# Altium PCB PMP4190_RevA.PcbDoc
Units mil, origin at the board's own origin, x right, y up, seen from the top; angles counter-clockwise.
Board outline 2303.15 x 1259.84 mil, 2 copper layers (Top Layer, Bottom Layer), stack 62 mil thick; 41 components, 17 nets, 91 pads, 28 vias.
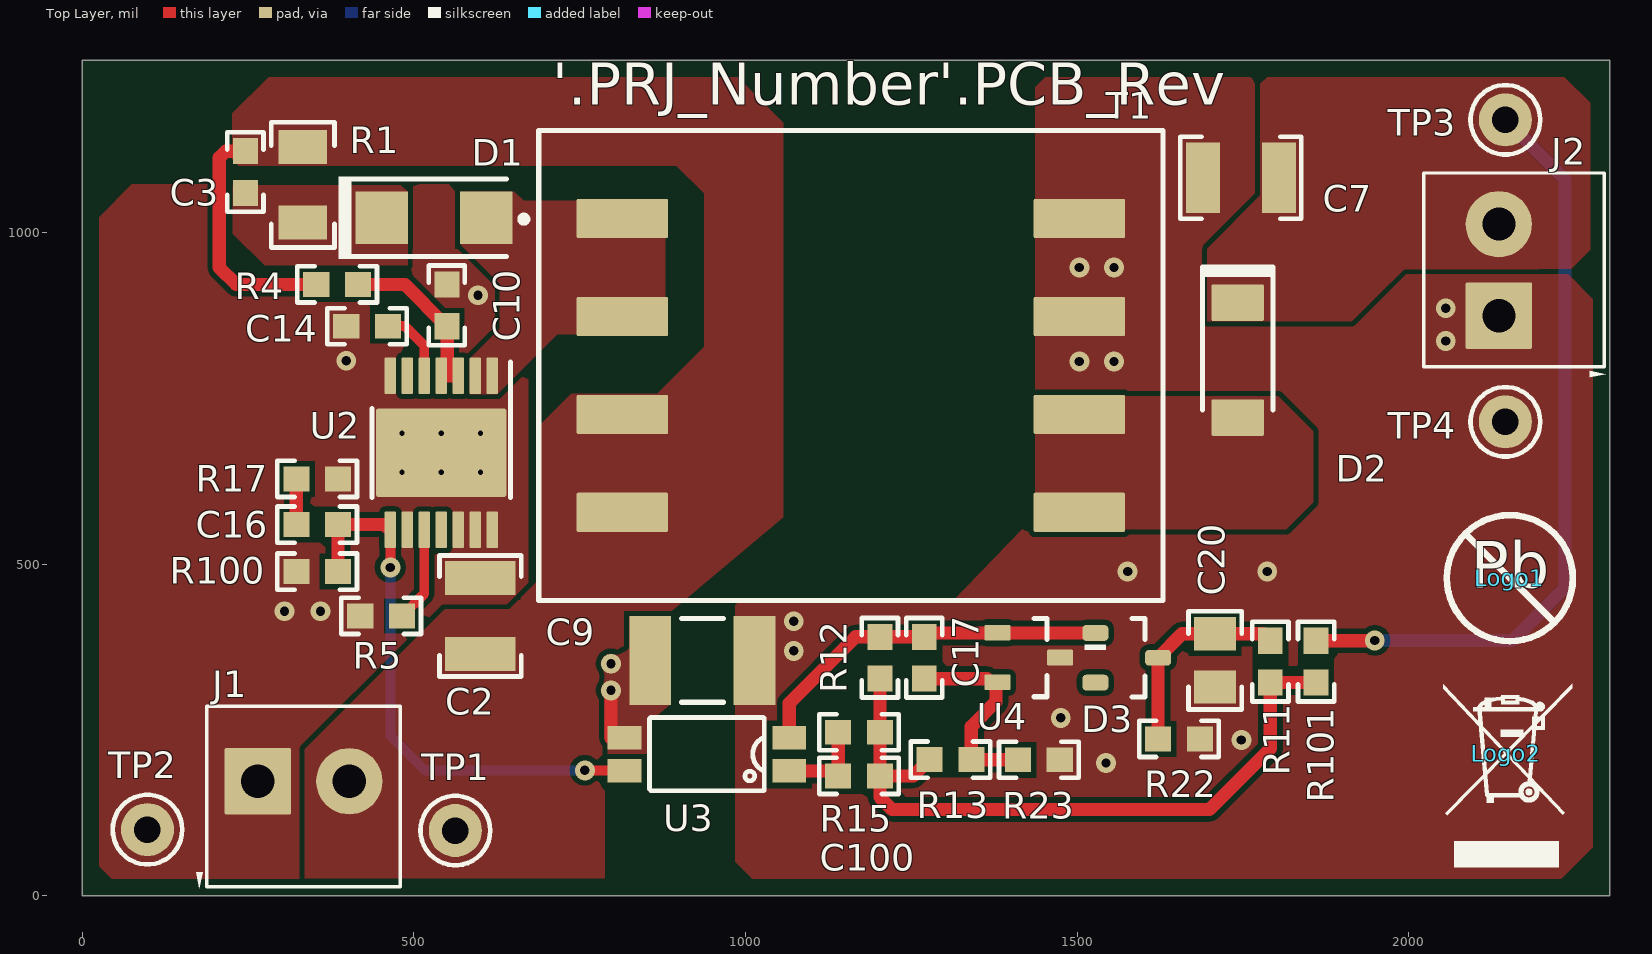
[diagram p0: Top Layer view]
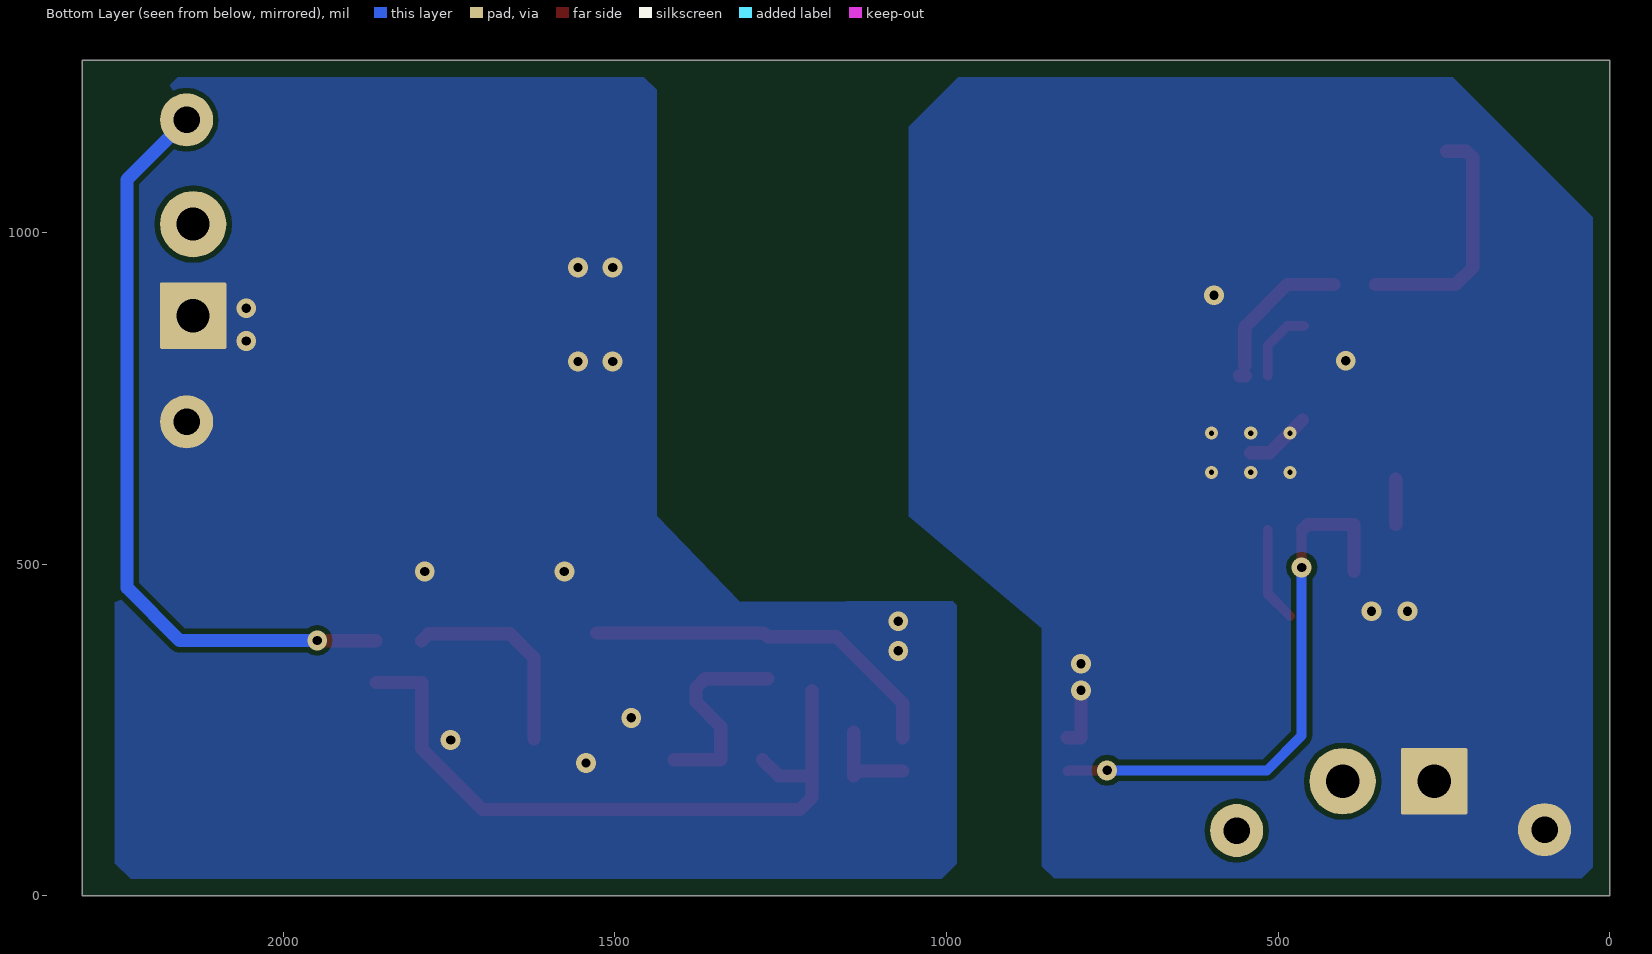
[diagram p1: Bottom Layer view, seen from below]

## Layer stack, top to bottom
Top Solder: solder mask 0.4, Solder Resist, Dk 3.5
Top Layer: signal copper 1.4
Dielectric1: core 59.2, FR-4, Dk 4.8
Bottom Layer: signal copper 1.4
Bottom Solder: solder mask 0.4, Solder Resist, Dk 3.5

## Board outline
0,0 2303.15,0 2303.15,1259.84 0,1259.84

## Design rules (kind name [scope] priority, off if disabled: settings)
AcuteAngle [All] p1: minimum=4.50000000000000E+0001 checktracksonly=FALSE
AssemblyTestPointUsage [All] p1: valid=2
BoardOutlineClearance BoardOutlineClearance_MountingHoles [OnCopper and InComponentClass('Mounting Holes')] p1: gap=25 ignorepadtopadclearanceinfootprint=FALSE
BoardOutlineClearance BoardOutlineClearance_Poly [OnCopper and InPoly] p2: gap=25 ignorepadtopadclearanceinfootprint=FALSE
BoardOutlineClearance [OnCopper and Not InComponentClass('Logo') and not InComponentClass('FiducialMark') and not InRegion(1000,500,4000,800)] p3: gap=25 ignorepadtopadclearanceinfootprint=FALSE
Clearance Clearance_Keepouts [((IsTrack Or IsArc) And Not InPoly) And IsFree and IsKeepOut vs ((IsTrack Or IsArc) And Not InPoly) And IsFree and IsKeepOut] p1: gap=0 ignorepadtopadclearanceinfootprint=FALSE
Clearance Clearance_Poly [InPolygon] p2: gap=8 ignorepadtopadclearanceinfootprint=FALSE except(0: Arc-Hole Track-Hole SMDPad-Hole THPad-Hole Via-Hole Fill-Hole Poly-Hole Region-Hole Text-Hole)
Clearance [All] p3: gap=7.87 ignorepadtopadclearanceinfootprint=FALSE except(0: Arc-Hole Track-Hole SMDPad-Hole THPad-Hole Via-Hole Fill-Hole Poly-Hole Region-Hole Text-Hole)
ComponentClearance ComponentClearance_MountingHoles_FiducialMarks [InComponentClass('Mounting Holes') vs InComponentClass('FiducialMark')] p1: gap=50 collisioncheckmode=3 verticalgap=10 showdistances=FALSE
ComponentClearance ComponentClearance_Shunt [InComponentClass('Header') vs InComponentClass('Shunt')] p2: gap=0 collisioncheckmode=3 verticalgap=0 showdistances=FALSE
ComponentClearance ComponentClearance_Logo [InComponentClass('Logo')] p3: gap=50 collisioncheckmode=3 verticalgap=10 showdistances=FALSE
ComponentClearance ComponentClearance_ScrewToNut [(HasFootprint('NY PMS 440 0025 PH')) vs (HasFootprint('Keystone_1902C'))] p4: gap=5 collisioncheckmode=3 verticalgap=10 showdistances=FALSE
ComponentClearance ComponentClearance_MountingHoles [InComponentClass('Mounting Holes')] p5: gap=250 collisioncheckmode=3 verticalgap=100000 showdistances=FALSE
ComponentClearance ComponentClearance_SmallPassives [HasFootprint('0201*') or HasFootprint('0402*') or HasFootprint('0508') or HasFootprint('0603*') or HasFootprint('0612') or HasFootprint('0805*') or HasFootprint('0815*') or HasFootprint('0830*') or HasFootprint('1206*') or HasFootprint('1210*') or HasFootprint('1808*') or HasFootprint('1812*') or HasFootprint('1825*') or HasFootprint('2010*') or HasFootprint('2220*') or HasFootprint('2225*') or HasFootprint('2512*') or HasFootprint('2728*') or HasFootprint('3518*') vs HasFootprint('0201*') or HasFootprint('0402*') or HasFootprint('0508') or HasFootprint('0603*') or HasFootprint('0612') or HasFootprint('0805*') or HasFootprint('0815*') or HasFootprint('0830*') or HasFootprint('1206*') or HasFootprint('1210*') or HasFootprint('1808*') or HasFootprint('1812*') or HasFootprint('1825*') or HasFootprint('2010*') or HasFootprint('2220*') or HasFootprint('2225*') or HasFootprint('2512*') or HasFootprint('2728*') or HasFootprint('3518*')] p6: gap=14.96 collisioncheckmode=3 verticalgap=10 showdistances=FALSE
ComponentClearance ComponentClearance_THtoSMT [IsThruComponent vs IsSMTComponent] p7: gap=15 collisioncheckmode=3 verticalgap=30 showdistances=FALSE
ComponentClearance ComponentClearance_THtoTH [IsThruComponent vs IsThruComponent] p8: gap=15 collisioncheckmode=3 verticalgap=30 showdistances=FALSE
ComponentClearance [All] p9: gap=15 collisioncheckmode=3 verticalgap=10 showdistances=FALSE
DiffPairsRouting [All] p1: maxlimit=100 minlimit=10 mostfreqgap=10 toplayer_minwidth=15 toplayer_maxwidth=15 toplayer_prefwidth=15 bottomlayer_minwidth=15 bottomlayer_maxwidth=15 bottomlayer_prefwidth=15 maxuncoupledlength=1000
FabricationTestPointUsage TestPointUsage [All] p1: valid=2 allowmultiple=FALSE
FabricationTestpoint Testpoint [All] p1: side=3 testpointundercomponent=TRUE minsize=40 maxsize=100 preferedsize=60 minholesize=0 maxholesize=40 preferedholesize=32 testpointgrid=1 allowsidetop=TRUE allowsidebottom=TRUE usegrid=TRUE gridtolerance=0.01
FanoutControl Fanout_LCC [IsLCC] p1: bgadir=Out bgaviamode=Centered fanoutstyle=Auto fanoutdirection=Alternating viagrid=1 // Fanout_LCC (Default Rule)
FanoutControl Fanout_BGA [IsBGA] p2: bgadir=Out bgaviamode=Centered fanoutstyle=Auto fanoutdirection=Alternating viagrid=1 // Fanout_BGA (Default Rule)
FanoutControl Fanout_Default [All] p4: bgadir=Out bgaviamode=Centered fanoutstyle=Auto fanoutdirection=Alternating viagrid=1 // Fanout_Default (Default Rule)
FanoutControl Fanout_Small [(CompPinCount < 5)] p5: bgadir=Out bgaviamode=Centered fanoutstyle=Auto fanoutdirection=OutThenIn viagrid=1 // Fanout_Small (Default Rule)
HoleSize [All] p1: absolutevalues=TRUE maxlimit=251 minlimit=7.87 maxpercent=80.000 minpercent=20.000
MinimumAnnularRing MinimumAnnularRing_ThermalPadVias [IsVia and InAnyComponent] p1: minimumring=5.91
MinimumAnnularRing [All] p2: minimumring=8
MinimumSolderMaskSliver MinimumSolderMaskSliver_Logo [InComponentClass('Logo') vs InComponentClass('Logo')] p1: minsoldermaskwidth=0.7
MinimumSolderMaskSliver [All] p2: minsoldermaskwidth=3.94
PlaneConnect [All] p1: planeconnectstyle=Direct reliefexpansion=10 reliefentries=4 reliefconductorwidth=10 reliefairgap=10
PolygonConnect [All] p1: connectstyle=Direct reliefconductorwidth=10 reliefentries=4 polygonreliefangle="90 Angle" airgapwidth=10
RoutingVias ThermalPadVias [IsVia and InAnyComponent] p1: holewidth=7.87 width=19.68 viastyle="Through Hole" minholewidth=7.87 minwidth=19.68 maxholewidth=12.99 maxwidth=23.62
RoutingVias [All] p2: holewidth=16 width=34 viastyle="Through Hole" minholewidth=7.87 minwidth=26 maxholewidth=40 maxwidth=65
SilkToBoardRegionClearance [Not ((IsComment or IsDesignator) And (Hide <> 'False')) and not InRegion(1000,500,4000,800)] p1:
SilkToSilkClearance SilkToSilkClearance_Pb-FreeLogo [(HasFootprint('Pb-Free_Overlay_Medium') OR HasFootprint('Pb-Free_Overlay_Small')) vs (HasFootprint('Pb-Free_Overlay_Medium') OR HasFootprint('Pb-Free_Overlay_Small'))] p1: silktosilkclearance=0
SilkToSilkClearance [All] p2: silktosilkclearance=4
SilkToSolderMaskClearance SilkToComponentPadClearance [IsPad and InAnycomponent] p1: minsilkscreentomaskgap=5 clearancetoexposedcopper=TRUE
SilkToSolderMaskClearance "Silk to Solder Mask Opening" [All] p2: minsilkscreentomaskgap=4 clearancetoexposedcopper=FALSE
SolderMaskExpansion [All] p1: expansion=1.97
Width [All] p1: maxlimit=100 minlimit=6 preferedwidth=10 checkconnectedcopper=TRUE
15 further rules are at their usual default settings.

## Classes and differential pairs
component class PMP4190_RevA: C2 C3 C7 C9 C10 C14 C16 C17 C20 C100 D1 D2 D3 J1 J2 R1 R4 R5 R11 R12 R13 R15 R17 R22 R23 R100 R101 T1 TP1 TP2 TP3 TP4 U2 U3 U4
component class Hardware: Logo1 Logo2 ZZ1 ZZ2 ZZ3 ZZ4
component class AssemblyNote: ZZ1 ZZ2 ZZ3 ZZ4

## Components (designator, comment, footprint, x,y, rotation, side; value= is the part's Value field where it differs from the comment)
C2 "GRM32ER71A226ME20L" 1210_270 600.39,421.91 r90 top value=22uF
C3 "C0603C102K5RACTU" 0603 246.06,1091.18 r270 top value=1000pF
C7 "GRM32ER71A226ME20L" 1210_270 1746.97,1082.68 r180 top value=22uF
C9 "1812GC472KA1" 1812 935.04,354.98 r180 top value=4700pF
C10 "C1608X7R1H104K080AA" 0603 549.79,890.27 r90 top value=0.1uF
C14 "CL10B101KB8NNNC" 0603 429.57,858.77 r180 top value=100pF
C16 "CGJ3E1X7R1E105K080AC" 0603 354.33,559.69 r180 top value=1uF
C17 "885012206089" 0603 1269.68,358.9 r270 top value=0.01uF
C20 "885012207025" 0805_HV 1707.97,354.98 r270 top value=4.7uF
C100 "C0603X223K5RACTU" 0603 1171.26,180.75 r180 top value=0.022uF
D1 "ES1B-13-F" SMA 530.35,1022.29 r0 top value=100V
D2 "RBS1LAM40ATR" FP-RBS1LAM40ATR_SOD128-MFG 1742.13,807.62 r270 top
D3 "BAS16LT1G" SOT-23 1574.8,358.9 r0 top value=100V
J1 "ED555/2DS" TERM_BLK_ED555-2DS 264.76,172.73 r0 top
J2 "ED555/2DS" TERM_BLK_ED555-2DS 2135.83,874.65 r90 top
Logo1 "Pb-Free Symbol" Pb-Free_Overlay_Medium 2152.48,478.99 r0 top
Logo2 "WEEE logo" WEEE_Minimum 2147.2,214.98 r0 top
R1 "RC1206FR-071KL" 1206 332.68,1071.98 r90 top value=1.00k
R4 "RC0603FR-0710RL" 0603 384.47,921.77 r180 top value=10.0
R5 "RC0603FR-0790K9L" 0603 450.79,421.91 r0 top value=90.9k
R11 "RC0603FR-071KL" 0603 1791.34,352.99 r270 top value=1.00k
R12 "RC0603FR-072KL" 0603 1202.76,358.9 r270 top value=2.00k
R13 "RC0603FR-0720KL" 0603 1309.06,205.36 r180 top value=20.0k
R15 "RC0603FR-07499RL" 0603 1171.26,246.69 r0 top value=499
R17 "RC0603FR-07499RL" 0603 354.33,628.58 r180 top value=499
R22 "RC0603FR-0710KL" 0603 1653.54,236.48 r180 top value=10.0k
R23 "RC0603FR-0720KL" 0603 1442.32,205.02 r0 top value=20.0k
R100 "RC0603FR-0749K9L" 0603 354.33,488.82 r0 top value=49.9k
R101 "RMCF0603ZT0R00" 0603 1860.24,352.99 r90 top value=0
T1 "G084001LF" FP-G084001LF_SMD8-MFG 1158.92,799.64 r270 top
TP1 "5000" Keystone5000 562.6,98.43 r90 top
TP2 "5001" Keystone5001 98.43,99.76 r90 top
TP3 "5000" Keystone5000 2145.67,1169.92 r90 top
TP4 "5001" Keystone5001 2145.67,714.64 r270 top
U2 "TPS61175PWP" PWP0014E_N 541.34,667.95 r270 top
U3 "TCMT1107" SOP-4 941.97,213.23 r180 top
U4 "TL431AIDBZR" DBZ0003A_N 1427.17,359.18 r0 top
ZZ1 "This Assembly Note is for PCB labels only" AssemblyNoteLabel 185,3938 r0 top
ZZ2 "These assemblies are ESD sensitive, ESD precautions shall be observed." AssemblyNote 185,3829.11 r0 top
ZZ3 "These assemblies must be clean and free from flux and all contaminants. Use of no clean flux is not acceptable." AssemblyNote 185,3740.56 r0 top
ZZ4 "These assemblies must comply with workmanship standards IPC-A-610 Class 2, unless otherwise specified." AssemblyNote 185,3652 r0 top

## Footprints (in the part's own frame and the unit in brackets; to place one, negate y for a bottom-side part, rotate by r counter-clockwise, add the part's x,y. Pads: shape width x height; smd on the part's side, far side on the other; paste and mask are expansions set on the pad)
0603 [mm] "0603 from SM-752 data"
  rect 1x0.95 smd: 1(-0.8,0) 2(0.8,0)
  silkscreen extent -1.52,-0.69 1.52,0.69, body extent -0.87,-0.47 0.87,0.47, height 1
0805_HV [mil] "0805 with 30mil clearance between pads"
  rect 50x63 smd: 1(-40,0) 2(40,0)
  silkscreen extent -74,-40 74,40, body extent -43,-29 43,29, height 57
1206 [mm] "1206 from SM-752 data"
  rect 1.3x1.85 smd: 1(-1.45,0) 2(1.45,0)
  silkscreen extent -2.4,-1.21 2.4,1.21, body extent -1.7,-0.9 1.7,0.9, height 1.35
1210_270 [mm] "1210"
  rect 1.3x2.7 smd: 1(-1.45,0) 2(1.45,0)
  silkscreen extent -2.32,-1.57 2.32,1.57, body extent -1.7,-1.35 1.7,1.35, height 2.7
1812 [mm]
  rect 1.6x3.4 smd: 1(-2,0) 2(2,0)
  silkscreen extent -0.8,-1.6 0.8,1.6, body extent -2.4,-1.7 2.4,1.7, height 1.35
AssemblyNote [mil] "Assembly Note"
AssemblyNoteLabel [mil] "Assembly Note for PCB Labels"
DBZ0003A_N [mm] "SOT23, 3-Leads, Body 2.9x1.3mm, Pitch 0.95mm, Lead Span 2.4mm, IPC Medium Density"
  rrect17% 1x0.6 smd: 1(-1.2,0.95) 2(-1.2,-0.95) 3(1.2,0)
  silkscreen extent 0.2,-1.5 0.7,1.5, body extent -1.26,-1.46 1.26,1.46, height 0.98
FP-G084001LF_SMD8-MFG [mm]
  rrect7% 1.5x3.5 smd paste+0 mask+0: 1(-5.625,-8.75) 2(-1.875,-8.75) 3(1.875,-8.75) 4(5.625,-8.75) 5(5.625,8.75) 6(1.875,8.75) 7(-1.875,8.75) 8(-5.625,8.75)
  silkscreen extent -9,-12.65 9,11.95, body extent -9.1,-12.05 9.1,12.05, height 0.25
FP-RBS1LAM40ATR_SOD128-MFG [mm]
  rrect7% 1.4x2 smd paste+0 mask+0: 1(-2.2,0) 2(2.2,0)
  silkscreen extent -3.56,-1.35 1.91,1.35, body extent -3,-1.45 3,1.45, height 0.25
Keystone5000 [mil] "For Keystone 500x miniature loop terminals"
  round 80 hole 40: 1(0,0)
  silkscreen extent -52,-52 52,52, body extent -49,-49 49,49, height 182
Keystone5001 [mil] "For Keystone 500x miniature loop terminals"
  round 80 hole 40: 1(0,0)
  silkscreen extent -52,-52 52,52, body extent -49,-49 49,49, height 182
Pb-Free_Overlay_Medium [mil]
  silkscreen extent -95,-95 95,95
PWP0014E_N [mm] "TSOP, 14-Leads, Body 5x4.4mm, Pitch 0.65mm, Thermal Pad 3x3 mm, IPC Medium Density"
  rrect22% 1.4x0.45 smd: 1(-2.95,1.95) 2(-2.95,1.3) 3(-2.95,0.65) 4(-2.95,0) 5(-2.95,-0.65) 6(-2.95,-1.3) 7(-2.95,-1.95) 8(2.95,-1.95) 9(2.95,-1.3) 10(2.95,-0.65) 11(2.95,0) 12(2.95,0.65) 13(2.95,1.3) 14(2.95,1.95)
  rrect6% 3.4x5 smd paste-2 mask-2: 15(0,0)
  rrect4% 2.46x2.31 on Top Paste: 15(0,0)
  rrect4% 2.46x2.31 on Top Solder: 15(0,0)
  silkscreen extent -3.47,-2.65 1.7,2.65, body extent -3.21,-2.5 3.21,2.5, height 1
SMA [mm] "Molded Diode, 2-Leads, Body 4.3x2.6mm, IPC Medium Density, based on OnSemi component dimensions and land pattern"
  rect 2x2 smd: 1(-2,0) 2(2,0)
  silkscreen extent -3.66,-1.57 2.79,1.57, body extent -2.6,-1.3 2.6,1.3, height 2.42
SOP-4 [mm] "Vishay Half Pitch Mini-Flat Package"
  rect 1.3x0.9 smd: 1(-3.15,0.635) 2(-3.15,-0.635) 3(3.15,-0.635) 4(3.15,0.635)
  silkscreen extent -2.2,-1.41 2.2,1.39, body extent -3.5,-1.4 3.5,1.4, height 2.12
SOT-23 [mm] "SOT23, 3-Leads, Body 2.9x1.3mm, Pitch 0.95mm, Lead Span 2.5mm, IPC Medium Density"
  rrect50% 1x0.6 smd: 1(-1.2,0.95) 2(-1.2,-0.95) 3(1.2,0)
  silkscreen extent -1.62,-1.5 0.7,1.5, body extent -1.16,-1.45 1.21,1.45, height 1
TERM_BLK_ED555-2DS [mil]
  rrect4% 100x100 hole 50: 1(0,0)
  round 100 hole 50: 2(138,0)
  silkscreen extent -93,-161 215,113, body extent -69,-150 207,106, height 323
WEEE_Minimum [mil] "WEEElie bin"
  silkscreen extent -95,-172 99,104

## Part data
C2 C7: library part CMP-0009219-2, "CAP, CERM, 22 uF, 10 V, +/- 10%, X7R, 1210", Cap_Case=1210, Manufacturer=MuRata, Supplier Part Number 1=490-11653-1-ND, TempCo=X7R, Tolerance_%=10%, Value1="0.002 ohm", Value2=10V, ValueDisplayed=22uF
C3: library part CMP-0006847-4, "CAP, CERM, 1000 pF, 50 V, +/- 10%, X7R, 0603", Cap_Case=0603, Manufacturer=Kemet, Supplier Part Number 1=399-1082-1-ND, TempCo=X7R, Tolerance_%=10%, Value1=Unknown, Value2=50V, ValueDisplayed=1000pF
C9: library part CMP-0009294-2, "CAP, CERM, 4700 pF, 2000 V, +/- 10%, X7R, 1812", Cap_Case=1812, Manufacturer=AVX, Supplier Part Number 1=581-1812GC472KA11A, TempCo=X7R, Tolerance_%=10%, Value1=Unknown, Value2=2000V, ValueDisplayed=4700pF
C10: library part CMP-0007044-5, "CAP, CERM, 0.1 uF, 50 V, +/- 10%, X7R, 0603", Cap_Case=0603, Manufacturer=TDK, Supplier Part Number 1=445-1314-1-ND, TempCo=X7R, Tolerance_%=10%, Value1="0.0296 ohm", Value2=50V, ValueDisplayed=0.1uF
C14: library part CMP-0083857-1, "CAP, CERM, 100 pF, 50 V,+/- 10%, X7R, 0603", Cap_Case=0603, Manufacturer="Samsung Electro-Mechanics", TempCo=X7R, Tolerance_%=10%, Value2=50V, ValueDisplayed=100pF
C16: library part CMP-0083856-1, "CAP, CERM, 1 µF, 25 V,+/- 10%, X7R, 0603", Cap_Case=0603, Manufacturer=TDK, TempCo=X7R, Tolerance_%=10%, Value2=25V, ValueDisplayed=1µF
C17: library part CMP-0750039-1, "CAP, CERM, 0.01 µF, 50 V,+/- 10%, X7R, 0603", Cap_Case=0603, Manufacturer="Wurth Elektronik", TempCo=X7R, Tolerance_%=10%, Value2=50V, ValueDisplayed=0.01µF
C20: library part CMP-0007690-2, "CAP, CERM, 4.7 uF, 10 V, +/- 10%, X7R, 0805", Cap_Case=0805, Manufacturer="Wurth Elektronik", Supplier Part Number 1=710-885012207025, TempCo=X7R, Tolerance_%=10%, Value1=Unknown, Value2=10V, ValueDisplayed=4.7uF
C100: library part CMP-0006984-4, "CAP, CERM, 0.022 uF, 50 V, +/- 10%, X7R, 0603", Cap_Case=0603, Manufacturer=Kemet, Supplier Part Number 1=399-5340-1-ND, TempCo=X7R, Tolerance_%=10%, Value1=Unknown, Value2=50V, ValueDisplayed=0.022uF
D1: library part CMP-0029022-2, "Diode, Superfast Rectifier, 100 V, 1 A, SMA", Manufacturer="Diodes Inc.", Value1=1A, Value2=0.92V
D2: library part CMP-0088101-2, "DIODE SCHOTTKY 20V 1A PMDTM", Manufacturer=Rohm
D3: library part CMP-0029193-2, "Diode, Switching, 100 V, 0.2 A, SOT-23", Manufacturer="ON Semiconductor", Value1=0.2A, Value2=1.25V
J1 J2: library part CMP-0074913-1, "Terminal Block, 3.5mm Pitch, 2x1, TH", Color=Grey, Current_A=6A, Manufacturer="On-Shore Technology", Supplier Part Number 1=ED1514-ND, Voltage_V=150V
Logo1: library part CMP-0074839-1
Logo2: library part CMP-0074769-1
R1: library part CMP-0017995-2, "RES, 1.00 k, 1%, 0.25 W, 1206", Manufacturer="Yageo America", Power_W=250mW, Supplier Part Number 1=311-1.00KFRCT-ND, TempCo="100 ppm/C", Tolerance_%=1%, Value2=0.25W, Value_Code=1k00, ValueDisplayed=1.00k
R4: library part CMP-0022751-4, "RES, 10.0, 1%, 0.1 W, 0603", Manufacturer=Yageo, Power_W=100mW, Supplier Part Number 1=311-10.0HRCT-ND, TempCo="100 ppm/C", Tolerance_%=1%, Value2=0.1W, Value_Code=10R0, ValueDisplayed=10.0
R5: library part CMP-0023314-5, "RES, 90.9 k, 1%, 0.1 W, 0603", Manufacturer=Yageo, Power_W=100mW, Supplier Part Number 1=311-90.9KHRCT-ND, TempCo="100 ppm/C", Tolerance_%=1%, Value2=0.1W, Value_Code=90k9, ValueDisplayed=90.9k
R11: library part CMP-0022895-5, "RES, 1.00 k, 1%, 0.1 W, 0603", Manufacturer=Yageo, Power_W=100mW, Supplier Part Number 1=311-1.00KHRCT-ND, TempCo="100 ppm/C", Tolerance_%=1%, Value2=0.1W, Value_Code=1k00, ValueDisplayed=1.00k
R12: library part CMP-0023000-5, "RES, 2.00 k, 1%, 0.1 W, 0603", Manufacturer=Yageo, Power_W=100mW, Supplier Part Number 1=311-2.00KHRCT-ND, TempCo="100 ppm/C", Tolerance_%=1%, Value2=0.1W, Value_Code=2k00, ValueDisplayed=2.00k
R13 R23: library part CMP-0022906-5, "RES, 20.0 k, 1%, 0.1 W, 0603", Manufacturer=Yageo, Power_W=100mW, Supplier Part Number 1=311-20.0KHRCT-ND, TempCo="100 ppm/C", Tolerance_%=1%, Value2=0.1W, Value_Code=20k0, ValueDisplayed=20.0k
R15 R17: library part CMP-0023141-5, "RES, 499, 1%, 0.1 W, 0603", Manufacturer=Yageo, Power_W=100mW, Supplier Part Number 1=311-499HRCT-ND, TempCo="100 ppm/C", Tolerance_%=1%, Value2=0.1W, Value_Code=499R, ValueDisplayed=499
R22: library part CMP-0022746-5, "RES, 10.0 k, 1%, 0.1 W, 0603", Manufacturer=Yageo, Power_W=100mW, Supplier Part Number 1=311-10.0KHRCT-ND, TempCo="100 ppm/C", Tolerance_%=1%, Value2=0.1W, Value_Code=10k0, ValueDisplayed=10.0k
R100: library part CMP-0023142-5, "RES, 49.9 k, 1%, 0.1 W, 0603", Manufacturer=Yageo, Power_W=100mW, Supplier Part Number 1=311-49.9KHRCT-ND, TempCo="100 ppm/C", Tolerance_%=1%, Value2=0.1W, Value_Code=49k9, ValueDisplayed=49.9k
R101: library part CMP-0023343-3, "RES, 0, 1%, 0.1 W, AEC-Q200 Grade 0, 0603", Manufacturer="Stackpole Electronics Inc", Power_W=100mW, Supplier Part Number 1=RMCF0603ZT0R00CT-ND, TempCo=ppm/C, Tolerance_%=1%, Value2=0.1W, Value_Code=0
T1: library part CMP-0087741-1, "FLYBACK TRANSFORMER", Manufacturer="GCI Technologies"
TP1 TP3: library part CMP-0055137-1, "Test Point, Miniature, Red, TH", Color=Red, Manufacturer=Keystone, Supplier Part Number 1=36-5000-ND
TP2 TP4: library part CMP-0055138-1, "Test Point, Miniature, Black, TH", Color=Black, Manufacturer=Keystone, Supplier Part Number 1=36-5001-ND
U2: library part CMP-0067201-2, "3-A High Voltage Boost Converter with Soft-start and Programmable Switching Frequency, PWP0014E (TSSOP-14)", Alternate Manufacturer="Texas Instruments"
U3: library part CMP-0006166-3, "Optocoupler, 3.75 kV, 80-160% CTR, SMT", Manufacturer=Vishay-Semiconductor, Supplier Part Number 1=TCMT1107CT-ND, Voltage_Isolation_Vrms=3.75kV
U4: library part CMP-0033090-1, "Adjustable Precision Shunt Regulator, 34 ppm / degC, 100 mA, -40 to 85 degC, 3-pin SOT-23 (DBZ), Green (RoHS & no Sb/Br)", Manufacturer="Texas Instruments", Rating=Catalog, Temp Coeff(Max)(ppm/ degree C)=92, Temp Coeff(Typ)(ppm/ degree C)=34
ZZ1: library part CMP-0003616-3
ZZ2: library part CMP-0077236-1
ZZ3: library part CMP-0077237-1
ZZ4: library part CMP-0077238-1

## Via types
v1: diameter 30, hole 14, Top Layer to Bottom Layer, 22 vias
v2: diameter 19.68, hole 7.87, Top Layer to Bottom Layer, tented both sides, 4 vias
v3: diameter 19.68, hole 7.87, Top Layer to Bottom Layer, 2 vias

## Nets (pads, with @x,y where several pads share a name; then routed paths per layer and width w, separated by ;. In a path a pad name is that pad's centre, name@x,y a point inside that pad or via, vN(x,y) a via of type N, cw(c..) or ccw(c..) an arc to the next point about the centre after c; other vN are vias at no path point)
NetC2_1: C2.1 C3.1 J1.2 R1.2 R4.2 T1.3 T1.4 TP1.1 | length 366
  Top Layer w20: C3.1 216.36,1122.68 206.69,1113.01 206.69,947.21 232.14,921.77 R4.2
NetC3_2: C3.2 D1.1 R1.1
NetC7_1: C7.1 D2.1 J2.2 R101.2 TP3.1 | length 1151.3
  Top Layer w20: R101.2 1948.25,384.49 v1(1948.82,385.06)
  Bottom Layer w20: v1(1948.82,385.06) 2156.46,385.06 2235.53,464.12 2235.53,1080.06 TP3.1
NetC10_1: C10.1 R4.1 U2.3 U2.4 | length 223.6
  Top Layer w20: R4.1@416.34,921.77 486.13,921.77 549.12,858.77 C10.1 ; U2.4@549.79,784.1 U2.3@558.39,784.1 ; 550.42,799.46 C10.1@550.42,854.96
NetC14_1: C14.1 U2.5 | length 112.4
  Top Layer w15: C14.1 486.78,858.77 515.75,829.81 U2.5
NetC16_1: C16.1 R100.2 U2.8 U3.4 | length 837.5
  Top Layer w15: v1(464.57,495.12) U2.8 ; v1(757.87,189.15) 817.03,189.15 U3.4
  Top Layer w20: R100.2 C16.1 455.55,559.69 U2.8@463.43,551.81
  Bottom Layer w15: v1(464.57,495.12) 464.57,241.54 516.96,189.15 v1(757.87,189.15)
NetC16_2: C16.2 R17.2 | length 68.9
  Top Layer w20: C16.2 R17.2
NetC17_1: C17.1 D3.1 R12.1 U3.2 U4.1 | length 557.6
  Top Layer w20: U3.2 1065.98,290.44 1165.94,390.4 R12.1 C17.1 1275.59,396.3 D3.1
NetC17_2: C17.2 R13.1 R23.1 U4.2 | length 307.9
  Top Layer w20: C17.2 1364.17,327.4 1377.67,313.9 1377.67,292.32 1340.55,255.2 R13.1 1340.89,205.02 R23.1
NetC20_1: C20.1 D3.3 R11.1 R22.2 | length 311
  Top Layer w20: R22.2 D3.3 1658.13,394.98 C20.1 1780.85,394.98 R11.1
NetC100_1: C100.1 R11.2 R12.2 R13.2 R15.2 R101.1 | length 1048.7
  Top Layer w20: R12.2@1202.76,309.69 R15.2 C100.1 ; R13.2 1252.95,180.75 C100.1 ; R101.1 R11.2 1791.34,222 1699.44,130.1 1221.46,130.1 1202.76,148.81 C100.1
NetC100_2: C100.2 R15.1 U3.1 | length 142.8
  Top Layer w20: U3.1 1132.28,188.23 C100.2 R15.1
NetD1_2: D1.2 T1.1 T1.2 U2.1 U2.2
NetD2_2: D2.2 T1.5 T1.6
NetR5_2: R5.2 U2.10 | length 143.8
  Top Layer w15: R5.2 515.75,455.37 U2.10
PGND: C2.2 C9.2 C10.2 C14.2 J1.1 R5.1 R17.1 R100.1 TP2.1 U2.7 U2.9 U2.12 U2.13 U2.14 U2.15@541.34,667.95 U3.3 | length 190.6
  Top Layer w20: U2.15@463.43,717.32 512.8,667.95 U2.15@541.34,667.95 ; v1(797.24,309.73) 797.24,238.23 U3.3
  other v1: 797.24,349.93 305.12,429.09 359.25,429.09 398.07,806.65 596.83,905.51
  other v2: 482.28,638.43 600.39,638.43 482.28,697.48 600.39,697.48
  other v3: 541.34,638.43 541.34,697.48
SGND: C7.2 C9.1 C20.2 J2.1 R22.1 R23.2 T1.7 T1.8 TP4.1 U4.3
  other v1: 1543.66,200.1 1747.64,234.84 1475.4,268.31 1072.83,369.37 1072.83,413.88 1576.15,488.82 1786.66,488.82 1503.41,805.56 1555.52,805.56 2055.83,836.61 2055.83,885.83 1503.41,947.29 1555.52,947.29
pads on no net: D3.2 U2.6 U2.11 U2.15@541.34,667.95

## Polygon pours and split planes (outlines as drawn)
NetC3_2 on Top Layer "TOP_LAYER_NETC3_2_P034" (solid, remove dead copper, pour order 34): 227.36,1071.5 227.36,998.03 275.08,950.31 490.59,950.31 490.59,1061.28 480.38,1071.5
NetD1_2 on Top Layer "TOP_LAYER_NETD1_2_P030" (solid, remove dead copper, pour order 30): 716.33,846.9 878.98,846.9 878.98,899.25 878.98,994.73 878.98,1047.61 665.53,1047.61 651.48,1061.66 571.49,1061.66 571.49,981.18 629.92,922.76 629.92,854.96 584.65,809.69 584.65,756.54 625.96,756.54
NetC2_1 on Top Layer "TOP_LAYER_NETC2_1_P014" (solid, remove dead copper, pour order 14): 226.38,1102.01 227.36,1101.03 895.67,1101.03 937.52,1059.18 937.52,827.91 866.82,757.21 737.53,757.21 688.98,708.66 688.98,477.01 643.72,431.75 546.46,431.75 335.63,220.92 335.63,26.17 625.16,26.17 787.92,26.17 788.36,287.11 885.83,286.84 885.83,427.54 1057.16,571 1057.16,1165.3 962.62,1259.84 306.45,1259.84 226.38,1179.77
NetC7_1 on Top Layer "TOP_LAYER_NETC7_1_P010" (solid, remove dead copper, pour order 10): 1696.32,975.83 1696.32,866.14 1914.11,866.14 1992.85,944.88 2244.09,944.88 2273.62,974.41 2273.62,1195.47 2234.74,1234.35 1776.34,1234.35 1776.34,1132.25 1776.34,1055.85
NetD2_2 on Top Layer "TOP_LAYER_NETD2_2_P004" (solid, remove dead copper, pour order 4): 1437.01,753.29 1437.01,552.69 1815.36,552.69 1855.99,593.32 1855.99,700.55 1803.25,753.29
SGND on Top Layer "TOP_LAYER_SGND_P038" (solid, remove dead copper, pour order 38): 984.25,51.22 1035.47,0 2204.72,0 2284.83,80.1 2284.83,892.32 1927.14,1250 1467.87,1250 1437.01,1219.14 1437.01,573.22 1312.13,443.19 984.25,445.1
PGND on Top Layer "TOP_LAYER_PGND_P048" (solid, remove dead copper, pour order 48): 61.34,8.51 19.68,50.16 19.68,1017.36 74.8,1072.48 609.25,1072.48 672.64,1009.1 672.64,467.76 718.49,421.91 885.83,421.91 885.83,287.91 856.3,263.18 856.3,45.32 819.49,8.51
no net on Top Layer "TOP_LAYER_NONET_P046" (solid, remove dead copper, pour order 46): 587.6,809.24
NetD1_2 on Top Layer "TOP_LAYER_NETD1_2_P042" (solid, remove dead copper, pour order 42): 587.6,809.24
SGND on Bottom Layer "BOTTOM_LAYER_SGND_P036" (solid, remove dead copper, pour order 36): 984.25,48.52 1007.28,25.49 2230.21,25.49 2253.94,49.21 2253.94,1139.44 2159.03,1234.35 1456.2,1234.35 1437.01,1215.16 1437.01,573.22 1312.13,443.19 984.25,445.1
PGND on Bottom Layer "BOTTOM_LAYER_PGND_P018" (solid, remove dead copper, pour order 18): 42.23,26.17 25.49,42.91 25.49,1023.17 262.16,1259.84 957.12,1259.84 1057.16,1159.81 1057.16,572.29 856.3,403.1 856.3,44.78 837.69,26.17

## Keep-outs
Keep-Out Layer:
  text ".Layer_Name" at 577,-858.49 h60

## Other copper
Top Layer:
  text ".Layer_Name" at 577,-858.49 h60
Bottom Layer:
  text ".Layer_Name" at 577,-858.49 h60

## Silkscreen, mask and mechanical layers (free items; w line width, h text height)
Top Overlay:
  text "'.PRJ_Number'.PCB_Rev" at 708.66,1171.26 h108.27
  text ".Layer_Name" at 577,-858.49 h60
Bottom Overlay:
  text ".Layer_Name" at 577,-858.49 h60
Top Paste:
  text ".Layer_Name" at 577,-858.49 h60
Bottom Paste:
  text ".Layer_Name" at 577,-858.49 h60
Top Solder:
  text ".Layer_Name" at 577,-858.49 h60
  text ".Layer_Name" at 577,-858.49 h60
Bottom Solder:
  text ".Layer_Name" at 577,-858.49 h60
Drill Guide:
  text ".Layer_Name" at 577,-858.49 h60
M1 Board Outline:
  the board outline again, w10
  text ".Layer_Name" at 577,-858.49 h60
M2 Board Dimensions:
  rectangle: 0,-275 125,-150
  rectangle: 125,-400 500,-275
  lines w7: 0,-275 1000,-275 ; 125,-400 125,-150 ; 250,-400 250,-150 ; 500,-400 500,-150 ; 750,-400 750,-150 ; 0,-400 1000,-400 1000,-150 0,-150 0,-400
  text ".Layer_Name" at 577,-858.49 h60
M3 3D STEP Top:
  text ".Layer_Name" at 577,-858.49 h60
M4 3D STEP Bottom:
  text ".Layer_Name" at 577,-858.49 h60
M5 Assembly Top:
  lines w10: -292,-930.17 6308,-930.17 ; -292,-726.83 6310,-726.83 ; -292,-523.5 -292,-1133.5 3713,-1133.5 6310,-1133.5 6310,-523.5 -291.5,-523.5 -291.5,-1133.5 1284,-1133.5 ; 2173,-1133.5 2173,-523.5 ; 3440,-726.83 3440,-523.5 ; 4280,-726.83 4280,-523.5 ; 4902,-1140 4902,-937.17
  text "COMPONENTS MARKED 'DNP' SHOULD NOT BE POPULATED." at 1153.5,-318.5 h60
  text "ASSEMBLY VARIANT:" at 1153,-434 h60
  text ".VariantName" at 2189,-434 h60
  text "PCB VIEWED FROM TOP SIDE" at -228.5,-655.67 h60
  text "BOARD #:" at 2248,-655.67 h60
  text ".PRJ_Number" at 2793.5,-655.67 h60
  text "REV:" at 3638,-655.67 h60
  text ".PCB_Rev" at 3929.5,-655.67 h60
  text "SVN REV:" at 4476,-655.67 h60
  text ".VersionControl_RevNumber" at 4982,-655.67 h60
  text "TID #:" at 2248,-859 h60
  text ".TID" at 2793.5,-859 h60
  text "PLOT NAME =" at -228.5,-1064.34 h60
  text ".plot_File_Name" at 577,-1064.34 h60
  text "GENERATED    :" at 2250,-1064.34 h60
  text ".Print_Date" at 3119.5,-1064.34 h60
  text ".Print_Time" at 3848.5,-1064.34 h60
  text "TEXAS INSTRUMENTS" at 5113,-1064.34 h60
M6 Assembly Bottom:
  lines w10: -292.5,-727.33 6309.5,-727.33 ; -290.5,-930.67 6309.5,-930.67 ; 1115.5,-1140.5 1115.5,-937.67 ; 1737.5,-727.33 1737.5,-524 ; 2577.5,-727.33 2577.5,-524 ; 3844.5,-1134 3844.5,-524 ; 4733.5,-1134 6309,-1134 6309,-524 -292.5,-524 -292.5,-1134 2304.5,-1134 6309.5,-1134 6309.5,-524
  text "COMPONENTS MARKED 'DNP' SHOULD NOT BE POPULATED." at 6102,-318 h60
  text ".VariantName" at 5058,-434 h60
  text "ASSEMBLY VARIANT:" at 6097,-434 h60
  text ".VersionControl_RevNumber" at 1035.5,-656.17 h60
  text "SVN REV:" at 1541.5,-656.17 h60
  text ".PCB_Rev" at 2088,-656.17 h60
  text "REV:" at 2379.5,-656.17 h60
  text ".PRJ_Number" at 3224,-656.17 h60
  text "BOARD #:" at 3769.5,-656.17 h60
  text "PCB VIEWED FROM BOTTOM SIDE" at 6246,-656.17 h60
  text ".TID" at 3224,-859.5 h60
  text "TID #:" at 3769.5,-859.5 h60
  text "TEXAS INSTRUMENTS" at 904.5,-1064.84 h60
  text ".Print_Time" at 2169,-1064.84 h60
  text ".Print_Date" at 2898,-1064.84 h60
  text "GENERATED    :" at 3767.5,-1064.84 h60
  text ".plot_File_Name" at 5440.5,-1064.84 h60
  text "PLOT NAME =" at 6246,-1064.84 h60
M9 Title Sheet:
  drawing of 57 lines, arcs and shapes, not listed
  text "1" at 739.84,8036.5 h70
  text "2" at 3235.5,8036.5 h70
  text "3" at 5724.84,8036.5 h70
  text "4" at 8231.51,8036.5 h70
  text "5" at 10730.5,8036.5 h70
  text "6" at 13235.5,8036.5 h70
  text "A" at -416.5,6893.5 h70
  text "A" at 14383.5,6893.5 h70
  text "B" at -416.5,4513.5 h70
  text "B" at 14383.5,4513.5 h70
  text "C" at -416.5,2138.5 h70
  text "C" at 14383.5,2138.5 h70
  text "PROJECT TITLE:" at 11343.5,277.5 h45
  text ".PRJ_Title" at 11393.5,144.17 h70
  text "DESIGNED FOR:" at 11343.5,-23.5 h45
  text ".PRJ_Customer" at 11393.5,-163.5 h70
  text "D" at -416.5,-231.5 h70
  text "D" at 14383.5,-231.5 h70
  text "FILE NAME:" at 11343.5,-323.5 h45
  text ".PCB_File_Name_No_Path" at 11393.5,-443.5 h70
  text "Texas Instruments (TI) and/or its licensors do not warrant the accuracy or completeness of this specification" at 6374,-605.34 h45
  text "ENGINEER:" at 11343.5,-613.5 h45
  text "LAYOUT BY:" at 12848.5,-613.5 h45
  text "or any information contained therein. TI and/or its licensors do not warrant that this design will meet" at 6329.01,-718 h45
  text ".PRJ_Engineer" at 11393.5,-768.49 h70
  text ".PCB_Layout" at 12899,-768.49 h70
  text "the specifications, will be suitable for your application or fit for any particular purpose, or will operate in" at 6329.01,-830.67 h45
  text ".Layer_Name" at 577,-858.49 h60
  text "ALTIUM DESIGNER VERSION:" at 12848.5,-923.5 h45
  text "an implementation. TI and/or its licensors do not warrant that the design is production worthy. You should" at 6329.01,-943.33 h45
  text "completely validate and test your design implementation to confirm the system functionality for your application." at 6374,-1056 h45
  text ".print_Scale" at 11393.5,-1056.83 h70
  text ".Application_BuildNumber" at 12899,-1056.83 h70
  text "1" at 739.84,-1263.5 h70
  text "2" at 3235.5,-1263.5 h70
  text "3" at 5724.84,-1263.5 h70
  text "4" at 8231.51,-1263.5 h70
  text "5" at 10730.5,-1263.5 h70
  text "6" at 13235.5,-1263.5 h70
M10 Fab Notes:
  drawing of 189 lines, arcs and shapes, not listed
  text "DESIGN INFORMATION" at 12382.02,6356.17 h60
  text "MIN. TRACK WIDTH:" at 11737.46,6224.05 h60
  text "8" at 12833.7,6224.05 h60
  text "MIL" at 12988.46,6224.05 h60
  text "MIN. CLEARANCE:" at 11737.46,6099.92 h60
  text "0.2" at 12773.7,6099.93 h60
  text "mm" at 12988.46,6099.92 h60
  text "MIN. VIA PAD SIZE:" at 11737.46,5975.8 h60
  text "24" at 12803.71,5975.8 h60
  text "MIL" at 12988.46,5975.8 h60
  text "0.05mm (2MIL)" at 12432.46,5845.9 h60
  text "MINIMUM ANNULAR RING" at 11408.23,5837.67 h60
  text "EXTERNAL" at 13140.46,5837.67 h60
  text "PER" at 11608.23,5727.55 h60
  text "IPC-D-275 CLASS 2 LEVEL C" at 11828.23,5727.54 h60
  text "MIL, HOLES" at 13316.46,5627.07 h60
  text "+/-" at 12924,5618.48 h60
  text "+/-" at 13778,5618.48 h60
  text "REGISTRATION TOLERANCES:" at 11408.23,5617.42 h60
  text "METAL" at 12608,5617.42 h60
  text "5" at 13184.2,5617.42 h60
  text "3" at 14017.2,5617.42 h60
  text "MIL" at 14133.46,5617.42 h60
  text "HOLE SIZE TOLERANCE (UNLESS OTHERWISE SPECIFIED):" at 11408.23,5519.1 h60
  text "+/-" at 13778,5516.23 h60
  text "3" at 14017.2,5515.17 h60
  text "MIL" at 14133.46,5515.17 h60
  text "MATERIAL:" at 11333.46,5377.52 h60
  text "FR-4 High Tg" at 12319.9,5249 h60
  text "X" at 12175.46,5241.01 h60
  text "FR-408" at 11754.46,5236.49 h60
  text "OTHER" at 13242.46,5236.49 h60
  text "62 MIL (1.6mm) +/-10%" at 12074.56,5093.46 h60
  text "X" at 11954.46,5091.01 h60
  text "THICKNESS:" at 11408.23,5085.24 h60
  text "OTHER" at 13359.46,5085.24 h60
  text "TOLERANCE:" at 11408.23,4946.92 h60
  text "X" at 12256.46,4946.92 h60
  text "ANSI IPC-6012 TYPE 3 CLASS 2" at 12434.48,4946.92 h60
  text "OTHER +/-" at 12434.46,4802.73 h60
  text "BOW & TWIST:" at 11408.23,4657.54 h60
  text "X" at 12256.46,4657.54 h60
  text "ANSI IPC-6012 TYPE 3 CLASS 2" at 12434.48,4657.54 h60
  text "OTHER +/-" at 12434.46,4510.85 h60
  text "DRILLING:" at 11333.46,4380.23 h60
  text "NC_DRILL FILES" at 13094.46,4275.04 h60
  text "REFERENCE:" at 11408.23,4271.1 h60
  text "X" at 12065.46,4271.01 h60
  text "AS SHOWN" at 12243.46,4271.1 h60
  text "X" at 12966.46,4271.1 h60
  text "OTHER" at 13392.46,4128.85 h60
  text "PTH COPPER THICKNESS:" at 11407.91,4125.32 h60
  text "X" at 12547.14,4125.32 h60
  text "20-30 um" at 12675.14,4125.32 h60
  text "BOARD FINISH:" at 11333.46,3977.73 h60
  text "SILKSCREEN:" at 11488.68,3867.6 h60
  text "X" at 12446.46,3867.6 h60
  text "TOP" at 12563.46,3867.6 h60
  text "X" at 12956.46,3867.6 h60
  text "BOTTOM" at 13074.46,3867.6 h60
  text "SILKSCREEN COLOR:" at 11488.68,3712.41 h60
  text "X" at 12445.46,3712.41 h60
  text "WHITE" at 12563.46,3712.41 h60
  text "OTHER" at 13074.46,3712.41 h60
  text "X" at 12576.46,3568.96 h60
  text "GREEN" at 12694.46,3568.96 h60
  text "OTHER" at 13312.46,3568.96 h60
  text "SOLDER RESIST COLOR:" at 11488.68,3562.1 h60
  text "X" at 12576.46,3414.71 h60
  text "MATTE" at 12694.46,3414.71 h60
  text "SEMI-GLOSS" at 13312,3414.07 h60
  text "IMMERSION GOLD (ENIG)" at 12394.46,3241.94 h60
  text "ENEPIG" at 13732,3234.72 h60
  text "SURFACE FINISH:" at 11333.46,3233.72 h60
  text "X" at 12216.46,3233.72 h60
  text "IMM. TIN/SILVER OR EQUIV" at 11663,3096.4 h60
  text "OTHER" at 13094.46,3092.47 h60
  text "ARRAY/PANEL:" at 11333.46,2937.09 h60
  text "CUT AND TRIM PER M1 BOARD OUTLINE" at 12394.46,2928.87 h60
  text "N.C. ROUTE" at 12394.46,2792.9 h60
  text "X" at 13082.46,2792.9 h60
  text "V. SCORE" at 13260.46,2792.9 h60
  text "CERTIFICATION:" at 11333.46,2663.77 h60
  text "MATERIALS AND WORKMANSHIP FOR ALL PCBS" at 12058.46,2663.77 h60
  text "TO MEET OR EXCEED THE REQUIREMENTS OF:" at 12058.46,2569.71 h60
  text "X" at 11695.97,2441.08 h60
  text "ANSI IPC-A-600F CLASS ->" at 11823.96,2441.08 h60
  text "X" at 13471.97,2441.08 h60
  text "2" at 13581.96,2441.08 h60
  text "1" at 13266.96,2439.58 h60
  text "3" at 13935.96,2439.58 h60
  text "X" at 12507.97,2293.39 h60
  text "RoHS" at 12635.96,2293.39 h60
  text "OTHER" at 13280.36,2293.39 h60
  text "PER ORDER" at 13677.42,2293.39 h60
  text "ALL BOARDS MUST MEET OR EXCEED UL94-V0 REQUIREMENTS." at 11361,2139.57 h60
  text "PCB MUST BEAR THE UL94V-0 UL REGISTERED MATERIAL ID NUMBER" at 11361,2023.5 h60
  text "ADDITIONAL REQUIREMENTS:" at 11333.46,1854.08 h60
  text "MICROSECTION:" at 11408.23,1746.95 h60
  text "YES" at 12313.96,1746.95 h60
  text "REQUIRED" at 13175.46,1602.62 h60
  text "BARE BOARD ELEC. TEST:" at 11408.23,1599.76 h60
  text "NONE" at 12713.96,1599.76 h60
  text "X" at 13057.46,1599.76 h60
  text "PER ORDER" at 13767.46,1599.76 h60
  text "XX MIL VIAS REQUIRE NON-CONDUCTIVE FILL AND PLANARIZE" at 11576.38,1394.82 h59
  text "XX MIL VIAS REQUIRE CONDUCTIVE FILL AND PLANARIZE" at 11584.38,1290.84 h60
  text "OUTER XX MIL TRACES REQUIRE 50 OHM SINGLE-ENDED IMPEDANCE" at 11583.39,1127.46 h58
  text "LAYER 2 & 3 (INNER LAYERS) XX MIL WIDE, XX MIL SPACE / TRACES REQUIRE 100 OHM DIFFERENTIAL IMPEDANCE" at 11575.39,891.74 h60
  text ".Layer_Name" at 577,-858.49 h60
M11 Gerber Information:
  lines w10: -292,-930.17 6308,-930.17 ; -292,-726.83 6310,-726.83 ; -292,-523.5 -292,-1133.5 3713,-1133.5 6310,-1133.5 6310,-523.5 -291.5,-523.5 -291.5,-1133.5 1284,-1133.5 ; 2173,-1133.5 2173,-523.5 ; 3440,-726.83 3440,-523.5 ; 4280,-726.83 4280,-523.5 ; 4902,-1140 4902,-937.17
  text "ALL ARTWORK VIEWED FROM TOP SIDE" at -228.5,-655.67 h60
  text "BOARD #:" at 2248,-655.67 h60
  text ".PRJ_Number" at 2793.5,-655.67 h60
  text "REV:" at 3638,-655.67 h60
  text ".PCB_Rev" at 3929.5,-655.67 h60
  text "SVN REV:" at 4476,-655.67 h60
  text ".VersionControl_RevNumber" at 4982,-655.67 h60
  text "LAYER NAME =" at -228.5,-858.49 h60
  text "TID #:" at 2248,-859 h60
  text ".TID" at 2793.5,-859 h60
  text "PLOT NAME =" at -228.5,-1064.34 h60
  text ".plot_File_Name" at 577,-1064.34 h60
  text "GENERATED    :" at 2250,-1064.34 h60
  text ".Print_Date" at 3119.5,-1064.34 h60
  text ".Print_Time" at 3848.5,-1064.34 h60
  text "TEXAS INSTRUMENTS" at 5113,-1064.34 h60
M12 Stackup:
  drawing of 191 lines, arcs and shapes, not listed
  text "Layer" at 9811.59,7649.94 h60
  text "Name" at 10221.51,7649.94 h60
  text "Material" at 11151.25,7649.94 h60
  text "Thickness" at 12011.02,7649.94 h60
  text "Constant" at 12660.85,7649.94 h60
  text "Board Layer Stack" at 13230.71,7649.94 h60
  text "1" at 9811.59,7529.94 h60
  text "Top Overlay" at 10221.51,7529.94 h60
  text "2" at 9811.59,7409.94 h60
  text "Top Solder" at 10221.51,7409.94 h60
  text "Solder Resist" at 11151.25,7409.94 h60
  text "0.40mil" at 12011.02,7409.94 h60
  text "3.5" at 12660.85,7409.94 h60
  text "3" at 9811.59,7289.94 h60
  text "Top Layer" at 10221.51,7289.94 h60
  text "Copper" at 11151.25,7289.94 h60
  text "1.40mil" at 12011.02,7289.94 h60
  text "4" at 9811.59,7169.94 h60
  text "Dielectric1" at 10221.51,7169.94 h60
  text "FR-4" at 11151.25,7169.94 h60
  text "59.20mil" at 12011.02,7169.94 h60
  text "4.8" at 12660.85,7169.94 h60
  text "5" at 9811.59,7049.94 h60
  text "Bottom Layer" at 10221.51,7049.94 h60
  text "Copper" at 11151.25,7049.94 h60
  text "1.40mil" at 12011.02,7049.94 h60
  text "6" at 9811.59,6929.94 h60
  text "Bottom Solder" at 10221.51,6929.94 h60
  text "Solder Resist" at 11151.25,6929.94 h60
  text "0.40mil" at 12011.02,6929.94 h60
  text "3.5" at 12660.85,6929.94 h60
  text "7" at 9811.59,6809.94 h60
  text "Bottom Overlay" at 10221.51,6809.94 h60
  text ".Layer_Name" at 577,-858.49 h60
M13 Component Bodies Top:
  text ".Layer_Name" at 577,-858.49 h60
M14 Component Bodies Bottom:
  text ".Layer_Name" at 577,-858.49 h60
M15 Courtyards Top:
  text ".Layer_Name" at 577,-858.49 h60
M16 Courtyards Bottom:
  text ".Layer_Name" at 577,-858.49 h60
Drill Drawing:
  lines w10: 5336.09,3004.95 5391.34,3004.95 5363.72,2949.7 5336.09,3004.95 ; 5336.09,3074.02 5391.34,3074.02 5391.34,3129.27 5336.09,3129.27 5336.09,3074.02 ; 5336.09,3198.34 5363.72,3212.15 5391.34,3198.34 5377.53,3225.96 5391.34,3253.59 5363.72,3239.78 5336.09,3253.59 5349.9,3225.96 5336.09,3198.34 ; 5336.09,3336.47 5349.9,3336.47 5363.72,3322.66 5377.53,3336.47 5391.34,3336.47 5377.53,3350.28 5391.34,3364.1 5377.53,3364.1 5363.72,3377.91 5349.9,3364.1 5336.09,3364.1 5349.9,3350.28 5336.09,3336.47
  lines w12: 5286,2912.4 8517.49,2912.4 ; 5286,3409.68 8517.49,3409.68 ; 5623.86,2788.08 5623.86,3534 ; 5955.86,2788.08 5955.86,3534 ; 6592.43,2788.08 6592.43,3534 ; 6851.57,2788.08 6851.57,3534 ; 7226.72,2788.08 7226.72,3534 ; 7951.05,2788.08 7951.05,3534 ; 5286,2788.08 8517.49,2788.08 8517.49,3534 5286,3534 5286,2788.08
  text "Symbol" at 5360.59,3446.98 h72
  text "Quantity" at 5661.16,3446.98 h72
  text "Finished Hole Size" at 5993.16,3446.98 h72
  text "Plated" at 6629.72,3446.98 h72
  text "Hole Type" at 6888.86,3446.98 h72
  text "Drill Layer Pair" at 7264.02,3446.98 h72
  text "Hole Tolerance" at 7988.35,3446.98 h72
  text "6" at 5661.16,3322.66 h60
  text "7.87mil (0.200mm)" at 5993.16,3322.66 h60
  text "PTH" at 6629.72,3322.66 h60
  text "Round" at 6888.86,3322.66 h60
  text "Top Layer - Bottom Layer" at 7264.02,3322.66 h60
  text "22" at 5661.16,3198.34 h60
  text "14.00mil (0.356mm)" at 5993.16,3198.34 h60
  text "PTH" at 6629.72,3198.34 h60
  text "Round" at 6888.86,3198.34 h60
  text "Top Layer - Bottom Layer" at 7264.02,3198.34 h60
  text "4" at 5661.16,3074.02 h60
  text "40.00mil (1.016mm)" at 5993.16,3074.02 h60
  text "PTH" at 6629.72,3074.02 h60
  text "Round" at 6888.86,3074.02 h60
  text "Top Layer - Bottom Layer" at 7264.02,3074.02 h60
  text "4" at 5661.16,2949.7 h60
  text "50.00mil (1.270mm)" at 5993.16,2949.7 h60
  text "PTH" at 6629.72,2949.7 h60
  text "Round" at 6888.86,2949.7 h60
  text "Top Layer - Bottom Layer" at 7264.02,2949.7 h60
  text "36 Total" at 5661.16,2825.38 h60
  text ".Layer_Name" at 577,-858.49 h60
M17 Embedded Cavity:
  text ".Layer_Name" at 577,-858.49 h60
M18 Embedded Assembly:
  text ".Layer_Name" at 577,-858.49 h60
M19 Embedded Keepout:
  text ".Layer_Name" at 577,-858.49 h60

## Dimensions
0,-400 to 1000,-400 on M2 Board Dimensions
0,0 to 0,1259.84 on M2 Board Dimensions
0,0 to 2303.15,0 on M2 Board Dimensions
